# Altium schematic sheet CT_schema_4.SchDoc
size 573 x 363 mm
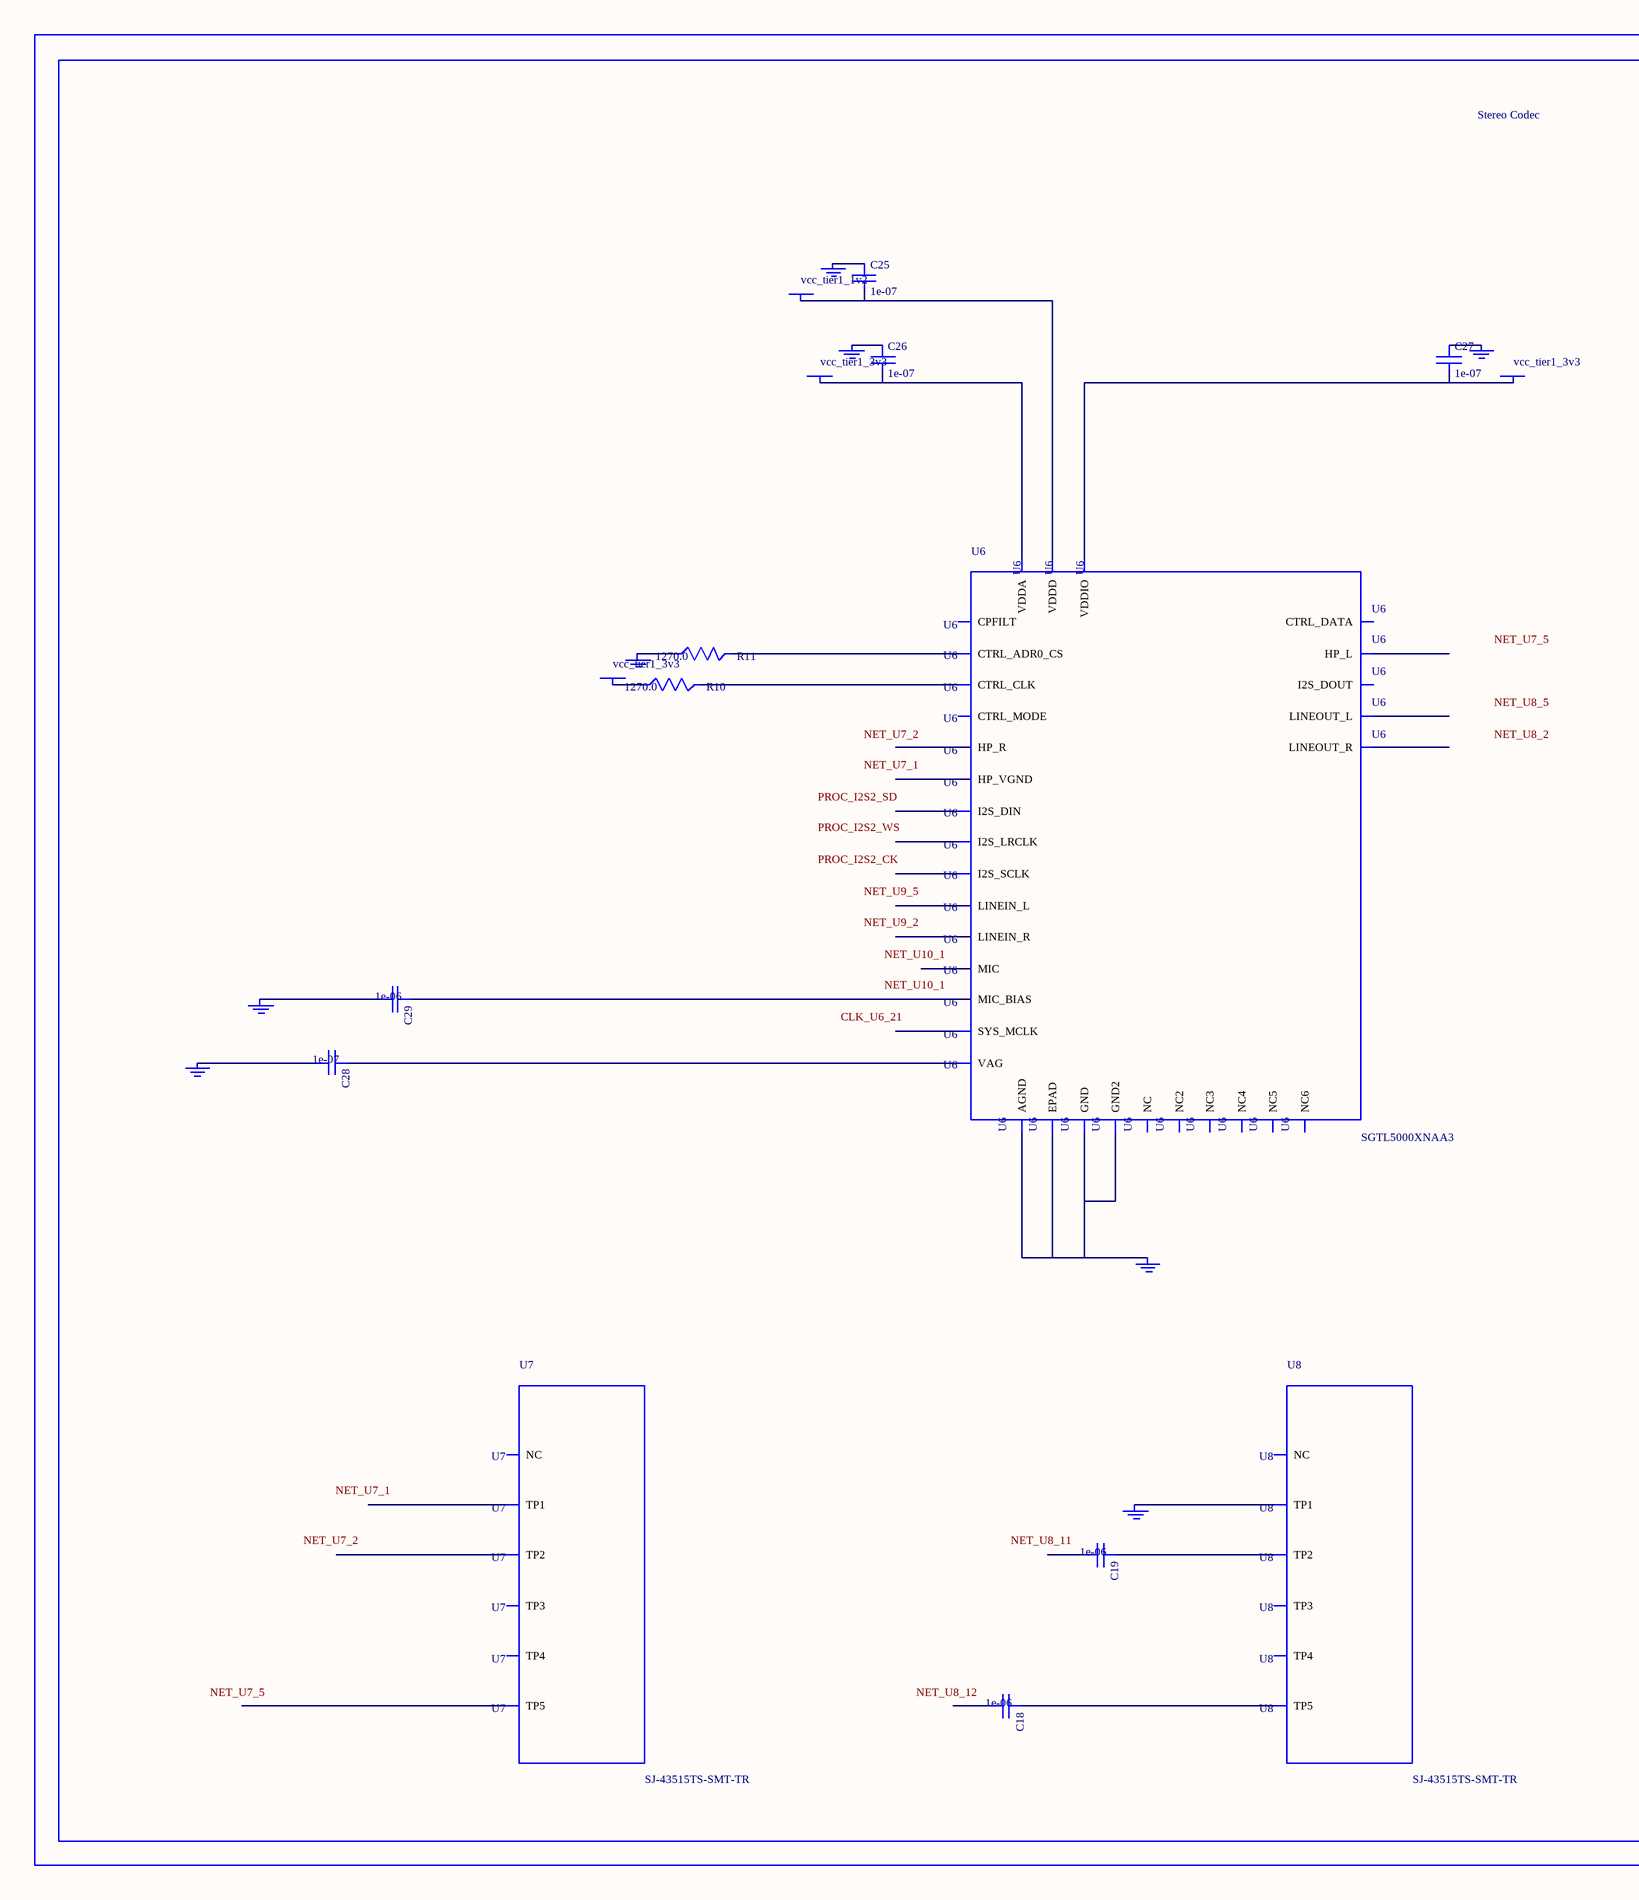
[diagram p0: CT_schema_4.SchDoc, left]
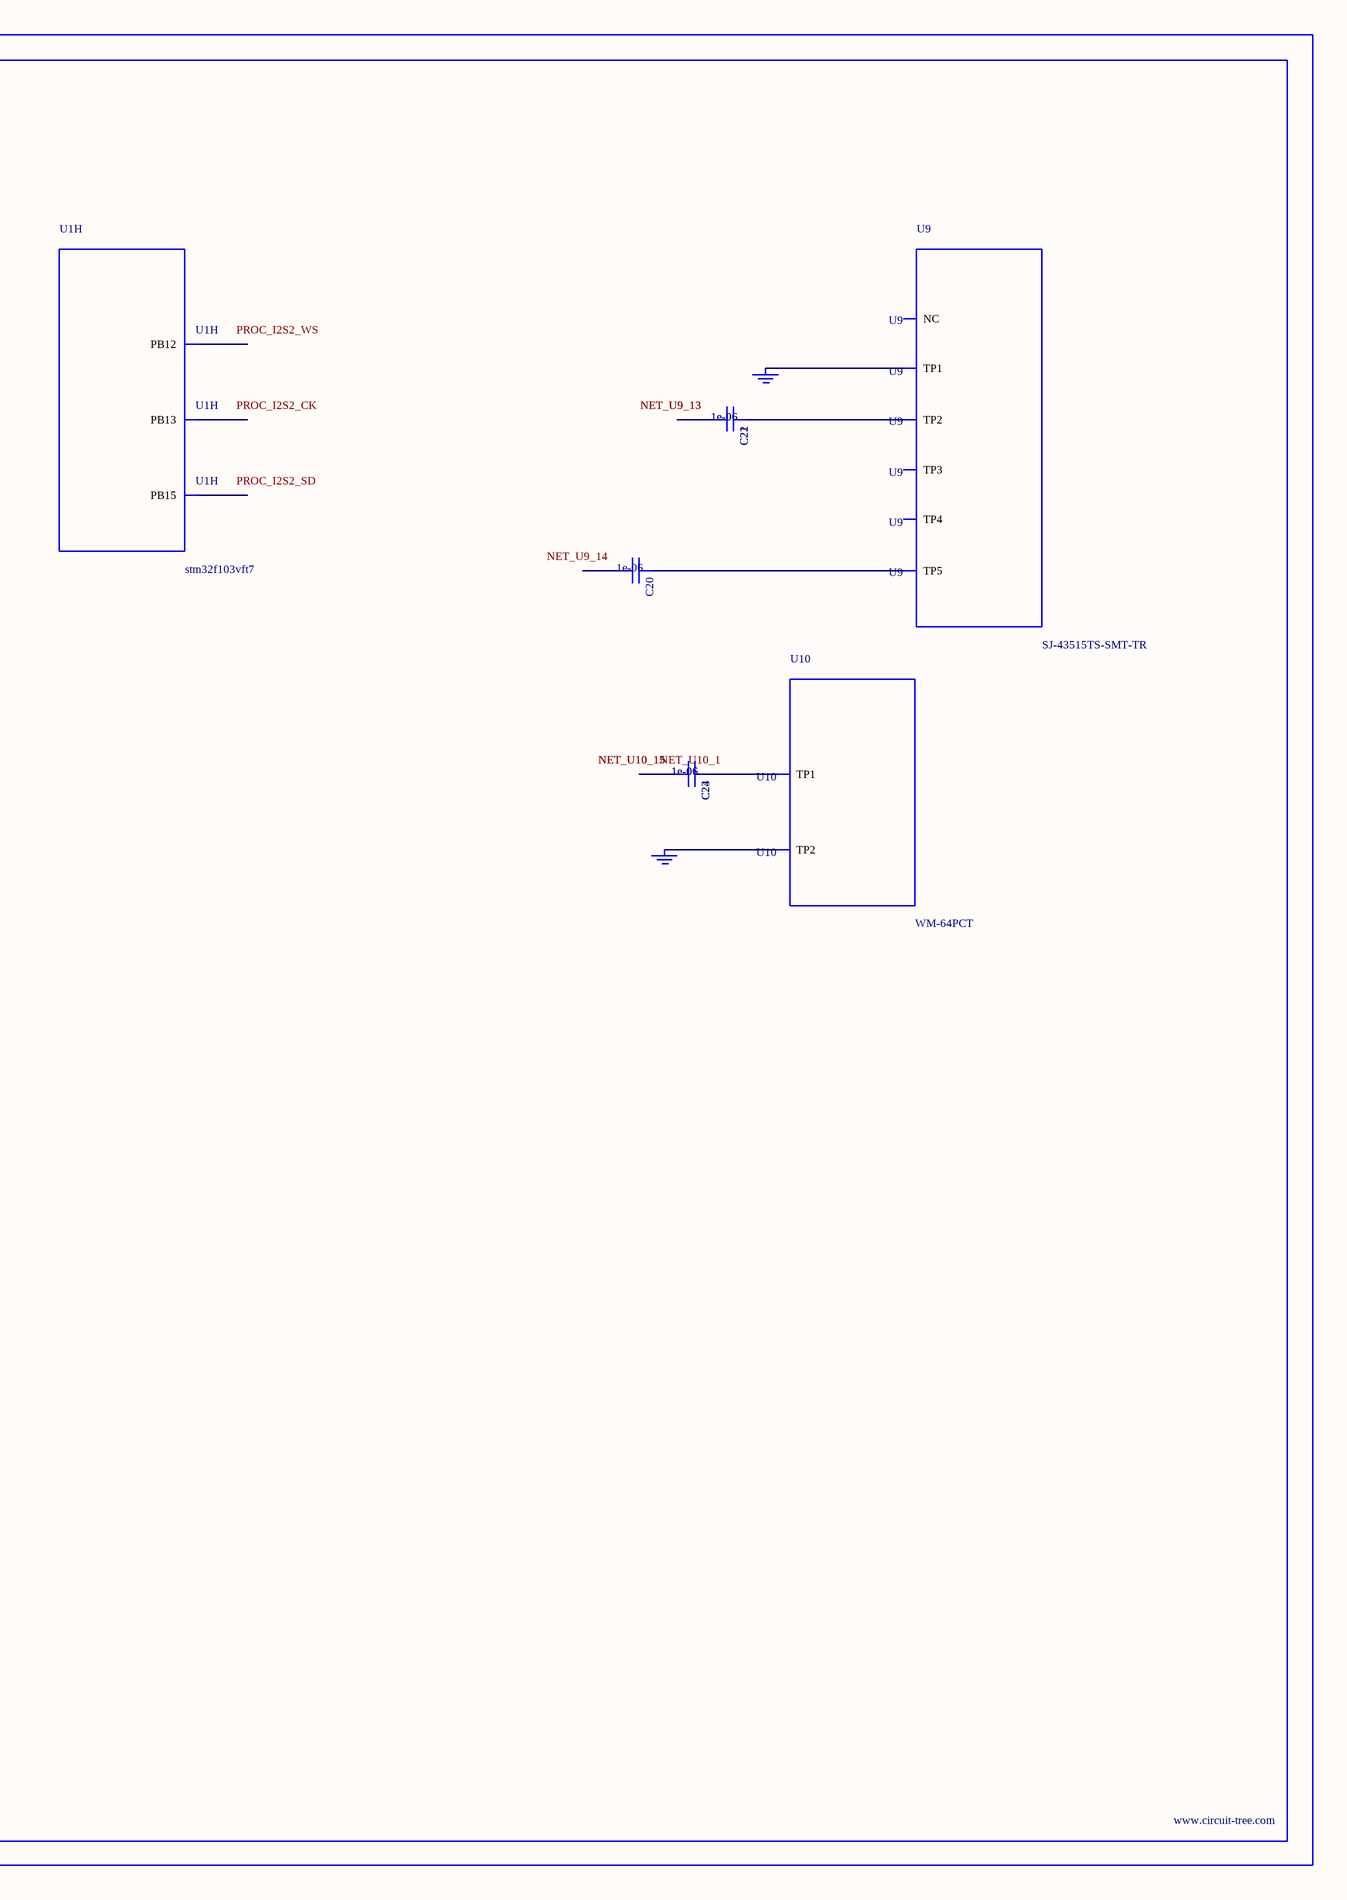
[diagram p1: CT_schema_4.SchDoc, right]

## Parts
BORDER3  (no value)
C18  1e-06  [C0603]
C19  1e-06  [C0603]
C20  1e-06  [C0603]
C21  1e-06  [C0603]
C22  1e-06  [C0603]
C23  1e-06  [C0603]
C24  1e-06  [C0603]
C25  1e-07  [C0402]
C26  1e-07  [C0402]
C27  1e-07  [C0402]
C28  1e-07  [C0402]
C29  1e-06  [C0603]
GND_INSTANCE_3_0  (no value)
GND_INSTANCE_3_1  (no value)
GND_INSTANCE_3_2  (no value)
GND_INSTANCE_3_3  (no value)
GND_INSTANCE_3_4  (no value)
GND_INSTANCE_3_5  (no value)
GND_INSTANCE_3_6  (no value)
GND_INSTANCE_3_7  (no value)
GND_INSTANCE_3_8  (no value)
GND_INSTANCE_3_9  (no value)
GND_INSTANCE_3_10  (no value)
POWER_INSTANCE_3_0  vcc_tier1_3v3
POWER_INSTANCE_3_1  vcc_tier1_3v3
POWER_INSTANCE_3_2  vcc_tier1_3v3
POWER_INSTANCE_3_3  vcc_tier1_1v2
R10  1270.0  [R0603]
R11  1270.0  [R0603]
U1  stm32f103vft7  [LQFP100]  (part H of 8)
U6  SGTL5000XNAA3  [QFN-32]
U7  SJ-43515TS-SMT-TR  [SJ-43515TS-SMT-TR]
U8  SJ-43515TS-SMT-TR  [SJ-43515TS-SMT-TR]
U9  SJ-43515TS-SMT-TR  [SJ-43515TS-SMT-TR]
U10  WM-64PCT  [WM-64PC]

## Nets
NetC18_1: C18.1 U8.5(TP5)
NetC19_1: C19.1 U8.2(TP2)
NetC20_1: C20.1 U9.5(TP5)
NetC21_1: C21.1 C22.1 U9.2(TP2)
NetC21_2: C21.2 C22.2
NetC23_1: C23.1 C24.1 U10.1(TP1)
NetC23_2: C23.2 C24.2
NetC25_1: C25.1 GND_INSTANCE_3_5.0(GND)
NetC25_2: C25.2 POWER_INSTANCE_3_3.0(PWR) U6.30(VDDD)
NetC26_1: C26.1 GND_INSTANCE_3_1.0(GND)
NetC26_2: C26.2 POWER_INSTANCE_3_0.0(PWR) U6.5(VDDA)
NetC27_1: C27.1 GND_INSTANCE_3_4.0(GND)
NetC27_2: C27.2 POWER_INSTANCE_3_1.0(PWR) U6.20(VDDIO)
NetC28_1: C28.1 U6.10(VAG)
NetC28_2: C28.2 GND_INSTANCE_3_2.0(GND)
NetC29_1: C29.1 U6.16(MIC_BIAS)
NetC29_2: C29.2 GND_INSTANCE_3_3.0(GND)
NetGND_INSTANCE_3_0_0: GND_INSTANCE_3_0.0(GND) U6.1(GND) U6.3(GND2) U6.7(AGND) U6.EXP(EPAD)
NetGND_INSTANCE_3_6_0: GND_INSTANCE_3_6.0(GND) R11.1
NetGND_INSTANCE_3_7_0: GND_INSTANCE_3_7.0(GND) U8.1(TP1)
NetGND_INSTANCE_3_8_0: GND_INSTANCE_3_8.0(GND) GND_INSTANCE_3_9.0(GND) U9.1(TP1)
NetGND_INSTANCE_3_10_0: GND_INSTANCE_3_10.0(GND) U10.2(TP2)
NetPOWER_INSTANCE_3_2_0: POWER_INSTANCE_3_2.0(PWR) R10.1
NetR10_2: R10.2 U6.29(CTRL_CLK)
NetR11_2: R11.2 U6.31(CTRL_ADR0_CS)

Not connected (* = marked no-connect by the designer): C18 2; C19 2; C20 2; U1 51(PB12) 52(PB13) 54(PB15); U6 2(HP_R) 4(HP_VGND) 6(HP_L) 8(NC) 9(NC2) 11(LINEOUT_R) 12(LINEOUT_L) 13(LINEIN_R) 14(LINEIN_L) 15(MIC) 17(NC3) 18(CPFILT) 19(NC4) 21(SYS_MCLK) 22(NC5) 23(I2S_LRCLK) 24(I2S_SCLK) 25(I2S_DOUT) 26(I2S_DIN) 27(CTRL_DATA) 28(NC6) 32(CTRL_MODE); U7 1(TP1) 2(TP2) 3(TP3) 4(TP4) 5(TP5) 6(NC); U8 3(TP3) 4(TP4) 6(NC); U9 3(TP3) 4(TP4) 6(NC)

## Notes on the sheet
- Labels drawn without touching a wire or pin: CLK_U6_21, NET_U7_1, NET_U7_2, NET_U7_5, NET_U8_2, NET_U8_5, NET_U8_11, NET_U8_12, NET_U9_2, NET_U9_5, NET_U9_14, NET_U10_1, PROC_I2S2_CK, PROC_I2S2_SD, PROC_I2S2_WS

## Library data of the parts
BORDER3 = BORDER_PAGE3
C18-C24 C29 = C0603C105K3RACTU
C25-C28 = C0402C104K3RACTU
GND_INSTANCE_3_0-GND_INSTANCE_3_10 = GND
POWER_INSTANCE_3_0-POWER_INSTANCE_3_3 = PWR
R10 R11 = RC0603FR-071K27L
